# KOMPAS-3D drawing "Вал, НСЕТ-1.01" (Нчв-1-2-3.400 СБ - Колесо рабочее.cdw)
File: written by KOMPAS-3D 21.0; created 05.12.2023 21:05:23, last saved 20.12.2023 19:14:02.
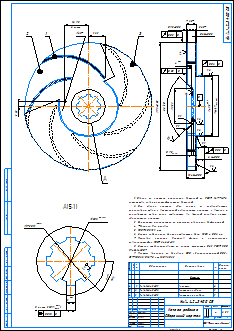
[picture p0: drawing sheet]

Sheet 1: A2, portrait

Document properties: Полное имя файла: D:\Точная технодинамика\04.12.2023\для отправки\центробежный насос нчв-1-2-3 (6) (готово)\Нчв-1-2-3.400 СБ - Колесо рабочее.cdw; Автор: zaycev_alexandr@mail.ru

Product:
- Part/product: (unnamed)
  - Component: Лопатка  | designation Нчв-1-2-3.401  | pos. 1  | Материал: Сталь 10Х17Н13М2Т ГОСТ 5632-72 (density 8000 kg/m3); Раздел спецификации: Детали; Форматы листов документа: A4
  - Component: Пластина задняя  | designation Нчв-1-2-3.402  | pos. 2  | Материал: Сталь 10Х17Н13М2Т ГОСТ 5632-72 (density 8000 kg/m3); Раздел спецификации: Детали; Форматы листов документа: A3
  - Component: Пластина передняя  | designation Нчв-1-2-3.403  | pos. 3  | Материал: Сталь 10Х17Н13М2Т ГОСТ 5632-72 (density 8000 kg/m3); Раздел спецификации: Детали; Форматы листов документа: A4
- Part/product: Вал  | designation НСЕТ-1.01
    Материал: Сталь 10Х17Н13М2Т(ЭИ448) ГОСТ 5632-2014 (density 8000 kg/m3)
    Масса: 2.553371
    Форматы листов документа: A4
    source file: НСЕТ-1.01 - Вал.cdw
- Part/product: Вал  | designation Нчв-1-2-3.400СБ
    Материал: Сталь 10Х17Н13М2Т(ЭИ448) ГОСТ 5632-2014 (density 8000 kg/m3)
    Масса: 2.553371
    Форматы листов документа: A4
    source file: НСЕТ-1.01 - Вал.cdw

Title block, sheet 1: Наименование: Колесо рабочее / Сборочный чертеж; Количество листов документа: 1; organisation: ООО "Точная технодинамика"; Форматы листов документа: A2; stored path: E:\Точная технодинамика\Задания\ООО «Красноленинский НПЗ»\Чертежи\НСЕТ-1.01 - Вал.cdw; Разработал: Дущенко; Т. контр.: Серков; Н. контр.: Юсупов; Утвердил: Елагин

Views: Разрез 6, Вид 7, Выносной элемент 9, Выносной элемент А, Выносной элемент
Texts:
  шаг
  Версия вида
  Тип вида
  Матрица вида
  Точка разреза
  Нчв-1-2-3 . 201
  Нчв-1-2-3 . 201
  Лопатка
  Нчв-1-2-3 . 203
  Нчв-1-2-3 . 203
  Пластина передняя
  Нчв-1-2-3 . 202
  Нчв-1-2-3 . 202
  Пластина задняя
  Нчв-1-2-3 . 401
  Нчв-1-2-3 . 401
  Нчв-1-2-3 . 402
  Нчв-1-2-3 . 402
  Нчв-1-2-3 . 403
  Нчв-1-2-3 . 403
  ElectricLineNodes
  es-vk-info-doc
  es-ov-info-doc
  es-tx-info-doc
Dimensions and other numbers on the sheet: 12,3; 68; 16,95; 6 мест; 3,15; 1; 2; 3; 88 30'; 25,2; 92±0,05; 42,5; 44; 0,95±0,05; 5,65; 0,65±0,05; 7,25; 6,2±0,05; 13,45±0,05; 4; 1,6; 0,05; 0,02; 17,5; 15; 8 мест; 3,3; 0,018; 6; 2,5:1

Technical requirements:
  Сварка по контуру прилегания деталей по ГОСТ 14771-76,
  катет шва равен меньшей толщине деталей.
  При сварке лопаток одна кромка их приваривается
  непрерывным швом к внутренней поверхности лопасти, а вторая -
  прерывистым швом через отверстия во второй половине листа,
  образующего лопасть.
  Применить мероприятия по снижению сварочных деформаций.
  *Размеры для справок.
  ГОСТ 30893.1 - m.
  Допуск радиального биения отверстия диам. 15Н8 - 0,02 мм.
  Числовые значения допусков формы и расположения
  поверхностей по ГОСТ 24643-81.
  Деталь отбалансировать по классу точности G6,3 ГОСТ ИСО
  Чертеж выполнен по договору ООО «Красноленинский НПЗ»
  №7710023/0167Д от 12.09.2023.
